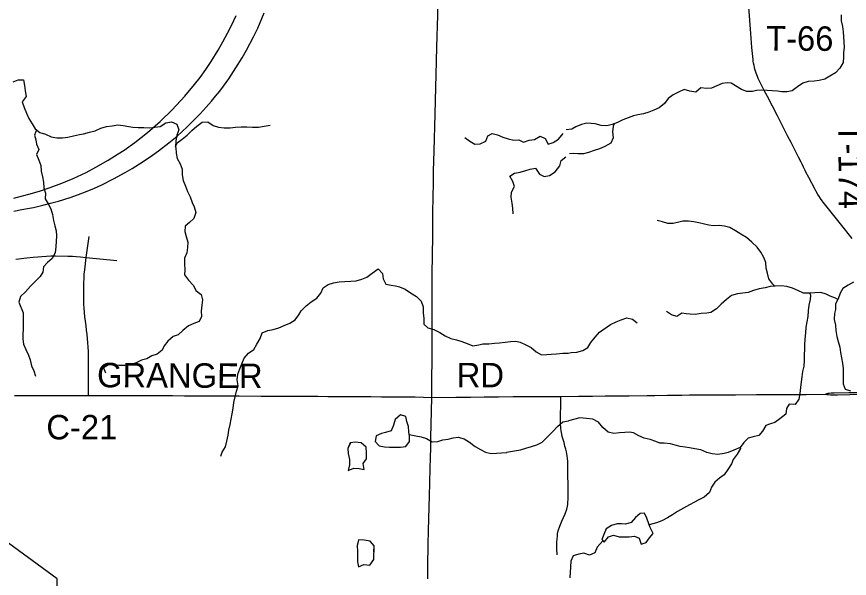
# Model space of a CAD drawing. Extents: x 0 to 34, y 0 to 22.
# Drawn here: x 3.395 to 5.327, y 15.452 to 16.757 of the extents above; entities that cross this region are included whole.
import ezdxf

# ---------------------------------------------------------------- set-up
doc = ezdxf.new("R2010")
doc.units = 0
for name, color, linetype in [('GM_X_County_Road', 7, 'Continuous'), ('GM_X_County_Road_Text', 7, 'Continuous'), ('GM_X_Interstate_Route', 7, 'Continuous'), ('GM_X_Minor_Lake', 7, 'Continuous'), ('GM_X_Minor_River', 7, 'Continuous'), ('GM_X_State_Route', 7, 'Continuous'), ('GM_X_Township_Road', 7, 'Continuous'), ('GM_X_Township_Road_Text', 7, 'Continuous'), ('SH_Text', 7, 'Continuous')]:
    doc.layers.add(name, color=color, linetype=linetype)

msp = doc.modelspace()

# ---------------------------------------------------------------- linework, layer by layer
at = {"layer": 'GM_X_County_Road'}
msp.add_line((5.2268, 15.8797), (5.2717, 15.8801), dxfattribs=at)
for points in [[(5.2717, 15.8801), (5.2732, 15.8808), (5.2758, 15.8817), (5.2782, 15.8822), (5.2804, 15.8825), (5.2853, 15.883), (5.292, 15.8833), (5.3259, 15.8838), (5.3555, 15.8843), (5.3639, 15.8845), (5.3708, 15.8848), (5.3794, 15.8853), (5.3885, 15.886), (5.3911, 15.8862), (5.3934, 15.8865), (5.3968, 15.887), (5.399, 15.8875), (5.4016, 15.8885)], [(3.3893, 15.8769), (3.5514, 15.877), (3.5616, 15.8771), (3.5839, 15.877), (3.6645, 15.8771), (3.6898, 15.877), (3.7216, 15.8769), (3.756, 15.8768), (3.7845, 15.8767), (3.8133, 15.8766), (3.8418, 15.8765), (3.8814, 15.8764), (3.911, 15.8762), (3.9619, 15.876), (4.0109, 15.8758), (4.0315, 15.8757), (4.0601, 15.8755), (4.0939, 15.8753), (4.1171, 15.8751), (4.1459, 15.8749), (4.1925, 15.8746), (4.2163, 15.8745), (4.2412, 15.8743), (4.2784, 15.874), (4.3071, 15.8738), (4.3192, 15.8738), (4.358, 15.8728), (4.4137, 15.8736), (4.4477, 15.8734), (4.4797, 15.8739), (4.5128, 15.8741), (4.5468, 15.8746), (4.5669, 15.8748), (4.5797, 15.8749), (4.6576, 15.8749), (4.6983, 15.8756), (4.7309, 15.8759), (4.7601, 15.8761), (4.7918, 15.8762), (4.8159, 15.8766), (4.8579, 15.8771), (4.8759, 15.8774), (4.905, 15.8781), (4.9386, 15.8783), (4.9563, 15.8784), (4.9947, 15.8786), (5.0314, 15.8788), (5.0627, 15.8789), (5.112, 15.8792), (5.1503, 15.8794), (5.2118, 15.8795), (5.2268, 15.8797)], [(5.2717, 15.8801), (5.2748, 15.8795), (5.2778, 15.8791), (5.283, 15.8787), (5.2996, 15.8789), (5.3284, 15.8794), (5.3562, 15.88), (5.3697, 15.8801), (5.3779, 15.8804), (5.3826, 15.8806), (5.3883, 15.8807), (5.3935, 15.8806), (5.396, 15.8804), (5.3979, 15.8799), (5.3995, 15.8793), (5.4016, 15.8782)]]:
    msp.add_lwpolyline(points, dxfattribs=at)
at = {"layer": 'GM_X_Interstate_Route'}
for points in [[(3.3878, 16.3358), (3.408, 16.3407), (3.4257, 16.3455), (3.4502, 16.3527), (3.4727, 16.3605), (3.4991, 16.3704), (3.5255, 16.3813), (3.556, 16.3955), (3.5786, 16.4073), (3.6073, 16.4238), (3.6304, 16.4382), (3.644, 16.4473), (3.6688, 16.4648), (3.6981, 16.4881), (3.7278, 16.5138), (3.7558, 16.5408), (3.7853, 16.5724), (3.8075, 16.5994), (3.8203, 16.616), (3.8337, 16.6344), (3.8461, 16.6527), (3.8624, 16.6793), (3.8733, 16.6983), (3.8842, 16.7187), (3.8931, 16.7364), (3.904, 16.7599)], [(3.3881, 16.3057), (3.4068, 16.3089), (3.4198, 16.3114), (3.4335, 16.3142), (3.455, 16.3189), (3.473, 16.3237), (3.4915, 16.3289), (3.5185, 16.3374), (3.538, 16.3442), (3.5545, 16.3504), (3.5752, 16.3589), (3.5922, 16.3664), (3.6197, 16.3807), (3.6466, 16.3949), (3.6624, 16.4041), (3.6886, 16.4209), (3.7099, 16.4351), (3.7241, 16.4456), (3.7476, 16.4639), (3.7668, 16.4798), (3.7906, 16.5016), (3.8205, 16.5316), (3.8345, 16.5471), (3.8465, 16.5608), (3.8563, 16.5728), (3.866, 16.5843), (3.8743, 16.5955), (3.887, 16.613), (3.9035, 16.638), (3.918, 16.6615), (3.928, 16.679), (3.9442, 16.7102), (3.954, 16.7307), (3.9637, 16.7532), (3.9692, 16.7664)]]:
    msp.add_lwpolyline(points, dxfattribs=at)
at = {"layer": 'GM_X_Minor_Lake'}
for points in [[(4.3061, 15.783), (4.3048, 15.793), (4.3042, 15.8048), (4.2998, 15.8165), (4.2977, 15.8286), (4.2852, 15.8322), (4.2733, 15.8213), (4.2693, 15.8083), (4.2635, 15.7953), (4.2504, 15.7909)], [(4.306, 15.7835), (4.3048, 15.793), (4.3042, 15.8048), (4.2998, 15.8165), (4.2977, 15.8286), (4.2852, 15.8322), (4.2733, 15.8213), (4.2693, 15.8083), (4.2635, 15.7953), (4.2504, 15.7909)], [(4.2504, 15.7909), (4.2413, 15.7889), (4.2293, 15.7834), (4.2265, 15.7704), (4.2358, 15.7599), (4.2483, 15.7579), (4.26, 15.7573), (4.2721, 15.7568), (4.2854, 15.757), (4.2982, 15.7588), (4.306, 15.7703), (4.3061, 15.783)], [(4.2504, 15.7909), (4.2413, 15.7889), (4.2293, 15.7834), (4.2265, 15.7704), (4.2358, 15.7599), (4.2483, 15.7579), (4.26, 15.7573), (4.2721, 15.7568), (4.2854, 15.757), (4.2982, 15.7588), (4.306, 15.7703), (4.3061, 15.7839)], [(4.1692, 15.7675), (4.1635, 15.7542), (4.1639, 15.7421), (4.167, 15.7288), (4.1673, 15.7159), (4.1643, 15.703), (4.1768, 15.7083), (4.1893, 15.7079), (4.201, 15.7053), (4.1987, 15.719)], [(4.169, 15.767), (4.1635, 15.7542), (4.1639, 15.7421), (4.167, 15.7288), (4.1673, 15.7159), (4.1643, 15.703), (4.1768, 15.7083), (4.1893, 15.7079), (4.201, 15.7053), (4.1987, 15.719)], [(4.1987, 15.719), (4.2063, 15.7303), (4.2063, 15.7432), (4.2059, 15.7573), (4.1938, 15.7671), (4.1802, 15.769), (4.1688, 15.767)], [(4.1987, 15.719), (4.2063, 15.7303), (4.2063, 15.7432), (4.2059, 15.7573), (4.1938, 15.7671), (4.1802, 15.769), (4.169, 15.767)], [(4.8647, 15.5704), (4.8617, 15.5789), (4.8575, 15.5919), (4.8514, 15.604), (4.8419, 15.6029), (4.8305, 15.5941), (4.8206, 15.5823), (4.8077, 15.5781), (4.7982, 15.5792), (4.7883, 15.5792), (4.7753, 15.575), (4.7628, 15.5678), (4.7575, 15.5541), (4.7526, 15.5423)], [(4.8647, 15.5704), (4.8617, 15.5789), (4.8575, 15.5919), (4.8514, 15.604), (4.8419, 15.6029), (4.8305, 15.5941), (4.8206, 15.5823), (4.8077, 15.5781), (4.7982, 15.5792), (4.7883, 15.5792), (4.7753, 15.575), (4.7628, 15.5678), (4.7575, 15.5541), (4.7526, 15.5423)], [(4.7526, 15.5423), (4.7583, 15.5366), (4.7685, 15.5492), (4.7799, 15.5526), (4.7933, 15.5488), (4.8028, 15.5488), (4.8165, 15.5492), (4.8283, 15.5507), (4.8397, 15.5458), (4.8439, 15.5321), (4.8553, 15.5356), (4.8637, 15.5462), (4.8716, 15.5565), (4.8647, 15.5704)], [(4.7526, 15.5423), (4.7583, 15.5366), (4.7685, 15.5492), (4.7799, 15.5526), (4.7933, 15.5488), (4.8028, 15.5488), (4.8165, 15.5492), (4.8283, 15.5507), (4.8397, 15.5458), (4.8439, 15.5321), (4.8553, 15.5356), (4.8637, 15.5462), (4.8716, 15.5565), (4.8648, 15.5702)], [(4.2244, 15.5138), (4.2245, 15.5281), (4.2147, 15.5387), (4.2011, 15.541), (4.1882, 15.5417), (4.1846, 15.5276)], [(4.2239, 15.5139), (4.2245, 15.5281), (4.2147, 15.5387), (4.2011, 15.541), (4.1882, 15.5417), (4.1848, 15.5285)], [(4.1845, 15.5281), (4.1844, 15.5281), (4.1846, 15.5266)], [(4.1845, 15.5281), (4.1859, 15.5156), (4.1856, 15.503), (4.186, 15.4909), (4.1882, 15.4788), (4.2007, 15.4845), (4.2143, 15.4833), (4.2238, 15.4962), (4.2234, 15.5099), (4.2238, 15.5103), (4.2244, 15.5138)], [(4.1846, 15.5276), (4.1859, 15.5156), (4.1856, 15.503), (4.186, 15.4909), (4.1882, 15.4788), (4.2007, 15.4845), (4.2143, 15.4833), (4.2238, 15.4962), (4.2234, 15.5099), (4.2238, 15.5103), (4.2244, 15.5138)]]:
    msp.add_lwpolyline(points, dxfattribs=at)
at = {"layer": 'GM_X_Minor_River'}
for points in [[(5.3082, 16.7611), (5.3082, 16.7474), (5.3109, 16.7345), (5.3124, 16.7219), (5.3132, 16.7105), (5.314, 16.6983), (5.3148, 16.6858), (5.3136, 16.6736), (5.3133, 16.6641), (5.3125, 16.6504), (5.3053, 16.6375), (5.2947, 16.6268), (5.2818, 16.6192), (5.27, 16.6123), (5.257, 16.6085), (5.2456, 16.607), (5.2319, 16.6062), (5.219, 16.6028), (5.2068, 16.5944), (5.1943, 16.5852), (5.1825, 16.5822), (5.17, 16.5822), (5.1604, 16.5841), (5.1479, 16.5848), (5.1361, 16.5856), (5.1239, 16.5863), (5.1117, 16.5859), (5.1022, 16.5836), (5.0889, 16.5836), (5.0771, 16.5878), (5.0527, 16.6029), (5.0432, 16.6037), (5.0318, 16.6018), (5.0196, 16.5968), (5.0075, 16.5911), (4.9953, 16.5899), (4.9824, 16.5918), (4.9706, 16.5819), (4.9569, 16.5842), (4.9439, 16.588), (4.9306, 16.5815), (4.9181, 16.5754), (4.9063, 16.5674), (4.8979, 16.5552), (4.8854, 16.5453), (4.8736, 16.54), (4.8618, 16.535), (4.8493, 16.5316), (4.8363, 16.5293), (4.8261, 16.5266), (4.8139, 16.5224), (4.8014, 16.5178), (4.7888, 16.511), (4.7766, 16.5064), (4.7641, 16.5037), (4.7508, 16.5045), (4.7374, 16.5082), (4.7279, 16.5086), (4.718, 16.5094), (4.7055, 16.5067), (4.6926, 16.501), (4.6831, 16.4956), (4.6701, 16.4941)], [(3.3865, 16.6057), (3.3985, 16.6101), (3.4106, 16.6103), (3.4131, 16.5975), (3.4144, 16.5846), (3.4169, 16.5717), (3.4077, 16.559), (3.4117, 16.5458), (3.4176, 16.533), (3.4231, 16.5206), (3.4305, 16.5082), (3.4376, 16.4966), (3.4487, 16.4877), (3.4612, 16.4841), (3.4746, 16.4779), (3.4875, 16.4754), (3.5007, 16.4757), (3.5135, 16.4774), (3.5267, 16.4803), (3.5403, 16.4832), (3.5501, 16.4853), (3.564, 16.4885), (3.5772, 16.4922), (3.5903, 16.4981), (3.6031, 16.5021), (3.616, 16.5039), (3.6295, 16.506), (3.6421, 16.5043), (3.6546, 16.5023), (3.6644, 16.5005), (3.6769, 16.4996), (3.6898, 16.4998), (3.7034, 16.4989), (3.7155, 16.5007), (3.728, 16.502), (3.7407, 16.5102), (3.7543, 16.5131), (3.7661, 16.5076), (3.7709, 16.4941), (3.7665, 16.4815), (3.7637, 16.4685), (3.7636, 16.4548)], [(3.7636, 16.4548), (3.7668, 16.464), (3.7788, 16.4726), (3.79, 16.4822), (3.8015, 16.4931), (3.8131, 16.5028), (3.8254, 16.5121), (3.8382, 16.5131), (3.8509, 16.5042), (3.863, 16.5006), (3.8763, 16.4986), (3.8899, 16.4992), (3.9024, 16.5002), (3.9156, 16.5015), (3.9288, 16.5014), (3.9421, 16.5008), (3.9557, 16.5007), (3.9693, 16.5028), (3.9829, 16.5054)], [(4.7816, 16.5083), (4.7789, 16.503), (4.7774, 16.4897), (4.779, 16.476), (4.7733, 16.463), (4.76, 16.4558), (4.747, 16.4501), (4.7349, 16.4466), (4.7219, 16.4417), (4.7098, 16.4382), (4.6968, 16.4386), (4.6873, 16.4393), (4.6778, 16.4389)], [(3.4376, 16.4966), (3.441, 16.494), (3.4359, 16.4817), (3.4391, 16.4708), (3.4405, 16.4609), (3.446, 16.4489), (3.4409, 16.4367), (3.446, 16.4242), (3.4508, 16.4118), (3.4514, 16.3985), (3.4543, 16.3849), (3.4568, 16.3724), (3.4577, 16.3596), (3.4614, 16.3475), (3.4608, 16.3338), (3.4679, 16.3222), (3.4737, 16.3109), (3.4781, 16.2973), (3.4803, 16.2837), (3.4835, 16.2712), (3.4864, 16.2595), (3.4869, 16.2481), (3.4859, 16.2223), (3.4839, 16.2086), (3.4773, 16.1956), (3.4661, 16.1863), (3.4568, 16.1759), (3.4555, 16.1633), (3.4493, 16.1537), (3.4381, 16.1429), (3.4266, 16.1309), (3.4151, 16.1178), (3.4032, 16.1074), (3.4, 16.0941), (3.4095, 16.0692), (3.4101, 16.0563), (3.4096, 16.0441), (3.4094, 16.0316), (3.4089, 16.0198), (3.4091, 16.0085), (3.4108, 15.9967), (3.4159, 15.9843), (3.4218, 15.9707), (3.4262, 15.9598), (3.4291, 15.9462), (3.4346, 15.9345), (3.4386, 15.9221)], [(4.4346, 16.4761), (4.4461, 16.4683), (4.4576, 16.4609), (4.4701, 16.4615), (4.4832, 16.4678), (4.4879, 16.48), (4.498, 16.4859), (4.5106, 16.4823), (4.5228, 16.4772), (4.5353, 16.4733), (4.5482, 16.4701), (4.5603, 16.4711), (4.571, 16.4656), (4.5838, 16.4703), (4.5966, 16.4721), (4.6097, 16.4799), (4.6208, 16.4744), (4.6278, 16.4612), (4.6399, 16.4645), (4.6522, 16.4727), (4.6626, 16.4854)], [(3.7636, 16.4548), (3.7644, 16.4526), (3.7646, 16.4397), (3.7671, 16.4276), (3.7738, 16.4152), (3.7789, 16.4031), (3.7791, 16.3898), (3.7809, 16.3766), (3.7864, 16.3638), (3.7915, 16.351), (3.797, 16.3386), (3.8018, 16.3254), (3.8069, 16.3156), (3.8102, 16.3024), (3.8059, 16.2886), (3.7954, 16.2793), (3.7854, 16.2704), (3.7848, 16.2583), (3.7884, 16.2462), (3.7921, 16.2334), (3.7915, 16.2212), (3.7899, 16.2083), (3.7844, 16.1964), (3.7843, 16.1827), (3.7849, 16.1691), (3.7843, 16.1573), (3.7933, 16.145), (3.8048, 16.133), (3.8103, 16.121), (3.8226, 16.1121), (3.8258, 16.0992), (3.8242, 16.0867), (3.8225, 16.0734), (3.8235, 16.0609), (3.818, 16.0494), (3.806, 16.0446), (3.7936, 16.0387), (3.7802, 16.0282), (3.7694, 16.0182), (3.7577, 16.0142), (3.7458, 16.0033), (3.7373, 15.9922), (3.7322, 15.9822), (3.721, 15.9729), (3.7086, 15.9693), (3.6966, 15.9626), (3.6846, 15.959), (3.6718, 15.9531), (3.659, 15.9487), (3.6454, 15.9469), (3.6326, 15.9467), (3.6205, 15.9476), (3.6076, 15.9482), (3.5963, 15.9415), (3.6011, 15.9295)], [(4.5471, 16.2993), (4.5465, 16.3122), (4.5447, 16.3243), (4.5422, 16.3379), (4.5432, 16.3497), (4.5497, 16.3627), (4.5465, 16.3741), (4.5395, 16.3865), (4.55, 16.3935), (4.5632, 16.3956), (4.5763, 16.4), (4.5861, 16.4028), (4.5989, 16.405), (4.6079, 16.3915), (4.6189, 16.3856), (4.631, 16.3881), (4.6445, 16.3966), (4.6552, 16.4105), (4.6587, 16.4231), (4.6688, 16.4316)], [(5.1544, 16.1314), (5.1493, 16.1361), (5.1405, 16.1478), (5.1371, 16.1611), (5.1344, 16.1733), (5.1336, 16.1862), (5.1283, 16.1976), (5.1214, 16.2102), (5.1134, 16.222), (5.1008, 16.2334), (5.0883, 16.244), (5.0753, 16.252), (5.0627, 16.2595), (5.0494, 16.2671), (5.0376, 16.2702), (5.0247, 16.272), (5.011, 16.2713), (5.0007, 16.2728), (4.9912, 16.275), (4.9779, 16.2781), (4.9661, 16.2807), (4.9539, 16.2818), (4.941, 16.2818), (4.9315, 16.2795), (4.9185, 16.2769), (4.906, 16.2765), (4.8938, 16.2803), (4.8808, 16.2837)], [(3.8681, 15.7361), (3.8718, 15.7456), (3.8795, 15.7583), (3.8823, 15.7712), (3.8854, 15.7849), (3.8871, 15.7967), (3.8903, 15.8097), (3.8924, 15.8222), (3.8948, 15.8348), (3.8968, 15.8477), (3.8985, 15.8607), (3.902, 15.8744), (3.9052, 15.8874), (3.9088, 15.8996), (3.9063, 15.9132), (3.9083, 15.9265), (3.9122, 15.9391), (3.917, 15.9509), (3.9224, 15.9639), (3.9328, 15.9755), (3.9451, 15.9837), (3.9521, 15.9967), (3.9598, 16.0097), (3.9645, 16.0227), (3.9773, 16.0279), (3.9901, 16.0308), (4.0029, 16.0344), (4.0156, 16.0396), (4.0288, 16.0455), (4.0411, 16.0529), (4.0492, 16.0644), (4.0547, 16.074), (4.0663, 16.0856), (4.0778, 16.0949), (4.0909, 16.1031), (4.1009, 16.1151), (4.106, 16.1273), (4.1176, 16.1347), (4.13, 16.1391), (4.1432, 16.1412), (4.1564, 16.1418), (4.1704, 16.1425), (4.1829, 16.1438), (4.1957, 16.1471), (4.2073, 16.1522), (4.22, 16.1615), (4.2338, 16.1713), (4.2439, 16.1608), (4.2456, 16.1479), (4.2511, 16.1359), (4.264, 16.1335), (4.2739, 16.1317), (4.2834, 16.1296), (4.2963, 16.1242), (4.3086, 16.1156), (4.3227, 16.1075), (4.3335, 16.0964), (4.3379, 16.0831), (4.3381, 16.0695), (4.3395, 16.0559), (4.3394, 16.0426), (4.349, 16.0344), (4.3627, 16.0301), (4.3764, 16.0235), (4.389, 16.0157), (4.4024, 16.0099), (4.4157, 16.0063), (4.4278, 16.0028), (4.4404, 15.9977), (4.4534, 15.9926), (4.4669, 15.9947), (4.4767, 15.9975), (4.4903, 15.9974), (4.5036, 15.9988), (4.5149, 15.9993), (4.5281, 16.0011), (4.5409, 16.0025), (4.5534, 16.0034), (4.5629, 16.0009), (4.5762, 15.9947), (4.5885, 15.9885), (4.6004, 15.9788), (4.613, 15.9715), (4.6254, 15.9724), (4.6353, 15.9734), (4.6477, 15.9743), (4.6621, 15.9754), (4.6749, 15.9756)], [(5.3365, 16.1401), (5.3243, 16.1336), (5.3122, 16.1256), (5.3057, 16.1146), (5.3012, 16.1016), (5.2951, 16.0898), (5.2947, 16.0769), (5.2928, 16.0674), (5.2917, 16.0537), (5.2948, 16.0408), (5.2959, 16.0279), (5.2979, 16.0145), (5.3013, 16.0024), (5.3048, 15.9891), (5.3067, 15.9769), (5.3086, 15.9644), (5.3109, 15.9522), (5.3124, 15.9393), (5.3128, 15.9267), (5.3128, 15.9172), (5.3125, 15.9043), (5.3175, 15.8917), (5.33, 15.8883)], [(5.3004, 16.1001), (5.2947, 16.1031), (5.2829, 16.1081), (5.2734, 16.1123), (5.2608, 16.1164), (5.2471, 16.1156), (5.2338, 16.1149), (5.2209, 16.1152), (5.2079, 16.1213), (5.195, 16.1266), (5.1817, 16.1304), (5.1687, 16.1319), (5.155, 16.1315), (5.1436, 16.13), (5.1314, 16.1273), (5.1177, 16.1246), (5.1048, 16.1212), (5.0926, 16.1166), (5.0801, 16.1147), (5.0672, 16.1131), (5.0538, 16.1093), (5.0417, 16.0998), (5.0295, 16.0891), (5.0189, 16.0785), (5.006, 16.0701), (4.9964, 16.0686), (4.9831, 16.0674), (4.9694, 16.0651), (4.958, 16.0658), (4.9485, 16.067), (4.9386, 16.0685), (4.9264, 16.0609), (4.9146, 16.0646), (4.9025, 16.0722)], [(5.2357, 16.115), (5.2369, 16.1099), (5.2361, 16.1004), (5.2331, 16.0867), (5.2316, 16.0738), (5.2305, 16.0609), (5.2282, 16.0479), (5.2259, 16.0358), (5.2252, 16.0224), (5.2241, 16.0084), (5.2229, 15.9947), (5.223, 15.9848), (5.2222, 15.9719), (5.2222, 15.9582), (5.2215, 15.9452), (5.2185, 15.9331), (5.2166, 15.9209), (5.2151, 15.9091), (5.214, 15.8958), (5.2125, 15.8817), (5.2098, 15.8684), (5.2015, 15.8562), (5.1878, 15.8573), (5.1813, 15.8467), (5.1798, 15.8338), (5.1661, 15.8231), (5.1543, 15.8143), (5.1444, 15.8116), (5.1334, 15.8071), (5.1255, 15.7941), (5.1171, 15.7839), (5.1042, 15.7808), (5.092, 15.7777), (5.0825, 15.7682), (5.0738, 15.756), (5.0593, 15.7499), (5.046, 15.745), (5.0365, 15.7423), (5.022, 15.74), (5.0091, 15.7419), (4.9962, 15.7449), (4.9828, 15.7506), (4.9688, 15.7532), (4.9558, 15.7555), (4.9459, 15.757), (4.9345, 15.7589), (4.9231, 15.7619), (4.9117, 15.7646), (4.8976, 15.7661), (4.8873, 15.7668), (4.8778, 15.7706), (4.8652, 15.7752), (4.8511, 15.7782), (4.8386, 15.7835), (4.8264, 15.7903), (4.8169, 15.7918), (4.8062, 15.7915), (4.7937, 15.7907), (4.7804, 15.7891), (4.7674, 15.7918), (4.7552, 15.8028), (4.7453, 15.8153), (4.7316, 15.8225), (4.7171, 15.824), (4.7019, 15.8253), (4.6753, 15.8184)], [(4.6747, 15.9756), (4.6815, 15.9773), (4.6949, 15.978), (4.7085, 15.9819), (4.7203, 15.9883), (4.7272, 16.0001), (4.737, 16.0123), (4.7473, 16.0241), (4.7731, 16.0424), (4.7857, 16.0481), (4.7979, 16.0531), (4.8108, 16.0577), (4.8237, 16.0546), (4.8348, 16.0463)], [(4.5316, 15.7453), (4.5639, 15.7513), (4.5763, 15.7545), (4.5891, 15.7589), (4.6019, 15.7626), (4.6139, 15.7688), (4.6265, 15.7812), (4.6388, 15.7939), (4.6499, 15.8048), (4.6622, 15.816), (4.6752, 15.8185)], [(4.3056, 15.7869), (4.3212, 15.7835), (4.3334, 15.7814), (4.3459, 15.7771), (4.3589, 15.7693), (4.3721, 15.7703), (4.3838, 15.7743), (4.3963, 15.776), (4.4079, 15.7785), (4.4193, 15.7802), (4.4329, 15.7767), (4.4456, 15.7685), (4.4586, 15.7585), (4.4712, 15.7519), (4.483, 15.7457), (4.496, 15.7421), (4.532, 15.7448)], [(5.0738, 15.756), (5.0745, 15.7538), (5.0666, 15.7412), (5.0571, 15.7283), (5.0533, 15.7184), (5.0453, 15.705), (5.0366, 15.6932), (5.0255, 15.6852), (5.0153, 15.6757), (5.0073, 15.6639), (5.0028, 15.6517), (4.9902, 15.6411), (4.9777, 15.635), (4.9678, 15.6296), (4.956, 15.6232), (4.9419, 15.6155), (4.9286, 15.6079), (4.9168, 15.5999), (4.9051, 15.5927), (4.8921, 15.5858), (4.8796, 15.5812), (4.8624, 15.5768)], [(4.7548, 15.5398), (4.7419, 15.5248), (4.7362, 15.5118), (4.7241, 15.5061), (4.7108, 15.5107), (4.699, 15.5088), (4.6864, 15.5046), (4.6811, 15.492), (4.68, 15.4791), (4.6783, 15.4534)]]:
    msp.add_lwpolyline(points, dxfattribs=at)
at = {"layer": 'GM_X_State_Route'}
msp.add_lwpolyline([(5.3337, 16.242), (5.3062, 16.276), (5.2693, 16.3222), (5.2665, 16.3261), (5.264, 16.3293), (5.2603, 16.3344), (5.2576, 16.3384), (5.2542, 16.3441), (5.2503, 16.3511), (5.2477, 16.356), (5.2328, 16.3836), (5.2265, 16.3956), (5.2244, 16.4), (5.2206, 16.4079), (5.2175, 16.4143), (5.2152, 16.419), (5.2094, 16.4304), (5.1989, 16.4512), (5.1918, 16.4647), (5.1835, 16.4807), (5.16, 16.5265), (5.1373, 16.5716), (5.1296, 16.5855), (5.1181, 16.6092), (5.1158, 16.6139), (5.1142, 16.6179), (5.1126, 16.6218), (5.1109, 16.6262), (5.1094, 16.6306), (5.108, 16.635), (5.107, 16.6392), (5.106, 16.6437), (5.1049, 16.6493), (5.1041, 16.654), (5.1036, 16.6576), (5.1009, 16.6858), (5.0983, 16.7177), (5.094, 16.7795)], dxfattribs=at)
at = {"layer": 'GM_X_Township_Road'}
for points in [[(4.358, 15.8728), (4.3587, 16.0036), (4.3593, 16.1711), (4.3594, 16.1911), (4.3601, 16.2593), (4.3604, 16.2735), (4.3607, 16.3036), (4.3611, 16.3362), (4.3618, 16.3736), (4.3624, 16.3988), (4.3629, 16.4218), (4.3637, 16.4453), (4.3644, 16.4739), (4.3651, 16.5022), (4.3657, 16.5308), (4.3666, 16.5627), (4.3675, 16.5927), (4.3683, 16.6229), (4.3689, 16.6535), (4.37, 16.6873), (4.3719, 16.7595), (4.3724, 16.7813)], [(3.5616, 15.8771), (3.5615, 15.9597), (3.5611, 15.9797), (3.5606, 15.9895), (3.5599, 16.0003), (3.5592, 16.009), (3.5581, 16.0191), (3.5568, 16.0291), (3.5556, 16.0391), (3.5543, 16.0498), (3.553, 16.0598), (3.5521, 16.0698), (3.5512, 16.08), (3.5507, 16.0893), (3.5505, 16.0994), (3.5504, 16.1106), (3.5506, 16.1398), (3.5512, 16.1493), (3.5516, 16.1587), (3.5526, 16.1689), (3.5563, 16.1977), (3.5626, 16.2462)], [(3.393, 16.1938), (3.4, 16.1945), (3.4059, 16.1953), (3.4116, 16.196), (3.4185, 16.197), (3.4328, 16.1984), (3.4437, 16.1995), (3.453, 16.2002), (3.4636, 16.2009), (3.4738, 16.2014), (3.4851, 16.2016), (3.5133, 16.201), (3.524, 16.2005), (3.5328, 16.1999), (3.5427, 16.1991), (3.5563, 16.1977), (3.6273, 16.191)], [(4.3485, 15.4514), (4.3489, 15.4809), (4.3498, 15.5312), (4.3506, 15.5634), (4.3529, 15.6445), (4.3536, 15.673), (4.3545, 15.7102), (4.3549, 15.7299), (4.3556, 15.7585), (4.3561, 15.7785), (4.358, 15.8728)], [(4.6487, 15.5074), (4.6485, 15.5216), (4.6483, 15.5369), (4.6487, 15.5435), (4.6495, 15.5511), (4.65, 15.5562), (4.6516, 15.5631), (4.6556, 15.5733), (4.6602, 15.5849), (4.6676, 15.6025), (4.6711, 15.6129), (4.6727, 15.62), (4.6736, 15.6241), (4.6739, 15.6276), (4.6744, 15.6375), (4.6736, 15.7247), (4.6724, 15.7367), (4.6704, 15.7465), (4.6693, 15.7524), (4.6671, 15.7597), (4.665, 15.7676), (4.6627, 15.775), (4.6607, 15.7816), (4.6595, 15.787), (4.6582, 15.795), (4.6576, 15.8009), (4.6571, 15.8111), (4.6576, 15.8749)]]:
    msp.add_lwpolyline(points, dxfattribs=at)
at = {"layer": 'SH_Text'}
msp.add_lwpolyline([(3.4887, 15.4514), (2.7956, 15.9593), (3.4887, 14.9614)], close=True, dxfattribs=at)

# ---------------------------------------------------------------- texts
at = {"layer": 'GM_X_County_Road_Text'}
for s, rotation, p in [('GRANGER', 359.7156, (3.5811, 15.8963)), ('RD', 0, (4.416, 15.8962)), ('C-21', 0, (3.4635, 15.7752))]:
    msp.add_text(s, height=0.05682, rotation=rotation, dxfattribs=at).set_placement(p)
at = {"layer": 'GM_X_Township_Road_Text'}
for s, rotation, p in [('T-66', 359.6465, (5.1337, 16.6786)), ('T-174', 270.2797, (5.3015, 16.5088))]:
    msp.add_text(s, height=0.05682, rotation=rotation, dxfattribs=at).set_placement(p)

doc.saveas('drawing.dxf')
